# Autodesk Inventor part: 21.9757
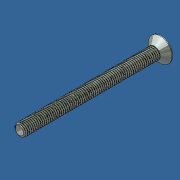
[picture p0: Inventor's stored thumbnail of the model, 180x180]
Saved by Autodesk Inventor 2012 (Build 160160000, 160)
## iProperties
Created: 2013-11
Part Number: 21.9757
Material: Steel
Document SubType Name: Modeling
Designer: Admin
Density: 7.85 g/cm^3
Mass: 8.0845 g
Surface Area: 16.1735 cm^2
Volume: 1.02987 cm^3
Description: M5x60 CSUNK
Vendor: S
Translation Standard: STEP AP203
FileName: 92125A230.step
PreProcessor: SolidWorks 2006233
PostProcessor: Build: 160, Release: 2012 RTM - Date: Tue 03/01/2011
Sent Units: inch
Uncertainty: 1e-05
Author: Admin
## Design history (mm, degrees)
node "92125A2301"
node "Base1"
body "Solid1"
